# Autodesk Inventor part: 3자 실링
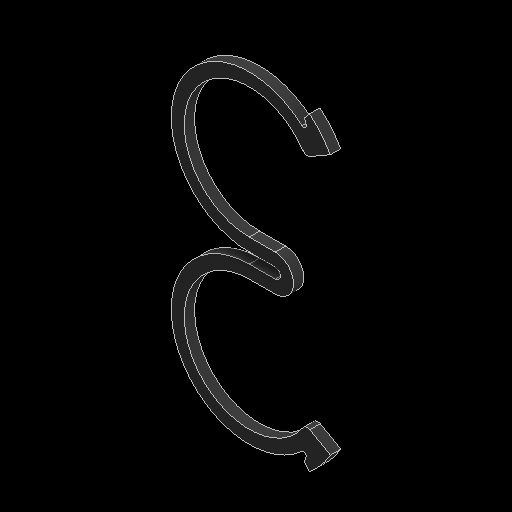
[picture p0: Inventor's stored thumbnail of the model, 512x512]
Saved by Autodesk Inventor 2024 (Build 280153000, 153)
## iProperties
Created: 2025-10
Part Number: 3자 실링
Material: 고무
Document SubType Name: Modeling
Designer: EDU03
Density: 0.93 g/cm^3
Appearance: 기본값
Author: jhkim
Sending System: Autodesk Inventor 2026
Preprocessor: ST-DEVELOPER v20.1
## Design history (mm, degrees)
node "3자 실링1"
node "솔리드2"
node "솔리드1"
